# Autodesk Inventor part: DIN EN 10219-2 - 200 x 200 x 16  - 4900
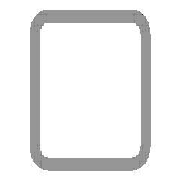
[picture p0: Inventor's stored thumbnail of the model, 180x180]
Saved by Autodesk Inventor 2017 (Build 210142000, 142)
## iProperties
IsCustomPart: 1
Created: 2017-11
Part Number: DIN EN 10219-2 - 200 x 200 x 16  - 4900
Material: Steel, Mild
Description: Cold formed welded structural hollow sections of non-alloy and fine grain structural steel
Document SubType Name: Modeling
Standard: DIN
Designer: iusti
Standard Revision: 2006-07
Standards Organization: DIN
Language: en-US
Size Designation: 200 x 200 x 16
Categories: <MemberInstance><Categories><Category DisplayName="Structural Shapes" InternalName="089c4875-fa83-4c05-b084-43b9cc11f5ed" Mnemonic="GRDR"><CategoryParameter Dis
Stock Number: 200 x 200 x 16
Density: 7.85 g/cm^3
Appearance: Semi-Polished
Mass: 410700 g
Surface Area: 65611.6 cm^2
Volume: 52318.5 cm^3
_CCFamilyMember: 103
_CCFamilyDisplayName: DIN EN 10219-2 (Square Hollow Section - Cold Formed) - Cold formed welded structural hollow sections of non-alloy and fine grain structural steel
_FrameMemberDoc: Frame Member File
_Version: 15.0.0
_GetPNFromCC: 1
G_L: 4900.000 mm
G_W: 200.000 mm
G_H: 200.000 mm
+38AB50A9-5FEF-434A-B58F-2C43C3F5CDA6+CUTDETAIL1: Cut
Author: iusti
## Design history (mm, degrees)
node "Start plane"
node "End plane"
sketch "Sketch"
  geometry: L1 (-100, -52)-(-100, 52); L2 (-52, 100)-(52, 100); L3 (100, 52)-(100, -52); L4 (52, -100)-(-52, -100); L5 (-52, 84)-(52, 84); L6 (84, 52)-(84, -52); L7 (52, -84)-(-52, -84); L8 (-84, -52)-(-84, 52); L9 (0, 293.918)-(0, -293.918) reference; L10 (-293.918, 0)-(293.918, 0) reference; A1 r 48 centre (-52, -52) between (-100, -52) and (-52, -100); A2 r 48 centre (-52, 52) between (-52, 100) and (-100, 52); A3 r 48 centre (52, 52) between (100, 52) and (52, 100); A4 r 48 centre (52, -52) between (52, -100) and (100, -52); A5 r 32 centre (-52, 52) between (-52, 84) and (-84, 52); A6 r 32 centre (52, 52) between (84, 52) and (52, 84); A7 r 32 centre (52, -52) between (52, -84) and (84, -52); A8 r 32 centre (-52, -52) between (-84, -52) and (-52, -84)
  constraints: 16 end point, 16 point on circle, 8 centre point, 8 tangent, 4 parallel, 3 equal radius, 2 perpendicular, 7 other
  dimensions: "d7" = 48 radius of A1 (= G_IR); "d10" = 200 distance between parallel lines of L2 L4 (= G_H); "d11" = 200 distance between parallel lines of L1 L3 (= G_W); "d12" = 16 distance between parallel lines of L3 L6 (= G_T); "d15" = 100 distance between parallel lines of L2 L10 (= 0.5 x d10); "d16" = 100 distance between parallel lines of L9 L3 (= 0.5 x d11)
extrude "Body" new body sketch "Sketch" stored distance "d3" = 4900 (= G_L); taper "d4" = 0 deg
node "Driven Length"
  sketch "Sketch3"
    geometry: L1 (0, 0)-(10, 0) reference
    constraints: 2 end point, 1 horizontal
  workplane "Work Plane3"
  sketch "Sketch4"
    geometry: L1 (-2, 0)-(12, 0) reference; L2 (-2, 4900)-(12, 4900) reference
    dimensions: "d18" = 4900 distance between parallel lines of L1 L2 (derived)
workplane "Work Plane4"
split "Split1"
body "Solid1"
other parameters: "G_W" = 200 [user parameter; used in 1 equation term], "G_H" = 200 [user parameter; used in 1 equation term], "G_T" = 16 [user parameter; used in 1 equation term], "G_IR" = 48 [user parameter; used in 1 equation term], "G_L" = 4900 (= d18) [user parameter; used in 1 equation term], "G_OFFSET_START" = 0 [user parameter; used in 1 equation term], "d13" = 0 (computed from G_OFFSET_START), "d17" = 90 deg
